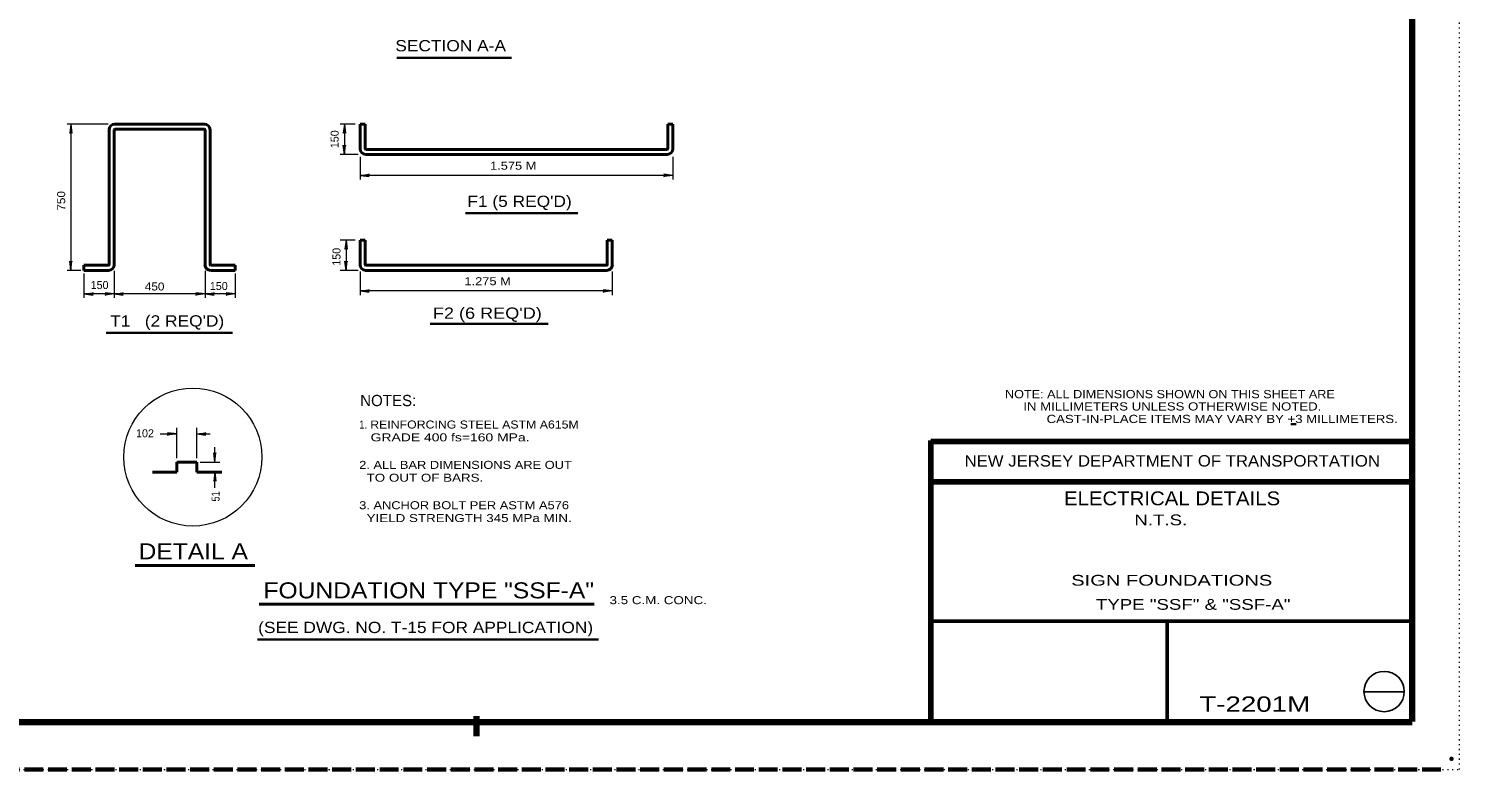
# Model space of a CAD drawing. Extents: x 312583 to 312854, y 144419 to 144597.
# Drawn here: x 312717.6 to 312853.5, y 144418.6 to 144489 of the extents above; entities that cross this region are included whole.
import ezdxf
from ezdxf.enums import TextEntityAlignment as Align

# ---------------------------------------------------------------- set-up
doc = ezdxf.new("R2010")
doc.units = 0
doc.header["$LTSCALE"] = 0.3
doc.header["$PDMODE"] = 32
doc.header["$PDSIZE"] = 0.15
doc.linetypes.add('DOTTED', pattern=[1.5, 0.3, -1.2])
doc.linetypes.add('LONG_DASHED', pattern=[7.5, 6, -1.5])
for name, color, linetype, lineweight in [('1', 7, 'Continuous', 40), ('10', 7, 'Continuous', 25), ('2', 7, 'Continuous', 13), ('62', 7, 'DOTTED', 13), ('63', 7, 'LONG_DASHED', 60)]:
    doc.layers.add(name, color=color, linetype=linetype, lineweight=lineweight)

msp = doc.modelspace()

# ---------------------------------------------------------------- linework, layer by layer
at = {"layer": '1', "lineweight": 158}
for p, q in [((312849, 144423.1446), (312849, 144585.0846)), ((312616.5, 144423.0846), (312849, 144423.0846)), ((312760.1396, 144421.7259), (312760.1396, 144423.6459))]:
    msp.add_line(p, q, dxfattribs=at)
at = {"layer": '1'}
for p, q in [((312734.2983, 144479.8873), (312725.7883, 144479.8873)), ((312749.0873, 144477.5489), (312749.0873, 144479.8873)), ((312749.0873, 144479.8873), (312749.5703, 144479.8873)), ((312749.5703, 144477.5489), (312749.5703, 144479.8873)), ((312778.3203, 144477.5489), (312778.3203, 144479.8873)), ((312778.3203, 144479.8873), (312778.7956, 144479.8873)), ((312778.7956, 144477.5489), (312778.7956, 144479.8873)), ((312725.2516, 144479.3429), (312725.2516, 144466.5319)), ((312725.7346, 144479.3429), (312725.7346, 144466.5319)), ((312734.2983, 144479.4043), (312725.7883, 144479.4043)), ((312734.3596, 144479.3429), (312734.3596, 144466.5319)), ((312734.835, 144479.3429), (312734.835, 144466.5319)), ((312749.6316, 144477.4876), (312778.259, 144477.4876)), ((312749.6316, 144477.0123), (312778.259, 144477.0123)), ((312749.0873, 144466.5319), (312749.0873, 144468.8626)), ((312749.0873, 144468.8626), (312749.5703, 144468.8626)), ((312749.5703, 144466.5319), (312749.5703, 144468.8626)), ((312772.5703, 144466.5319), (312772.5703, 144468.8626)), ((312772.5703, 144468.8626), (312773.0456, 144468.8626)), ((312773.0456, 144466.5319), (312773.0456, 144468.8626)), ((312725.1903, 144466.4706), (312722.8596, 144466.4706)), ((312722.8596, 144466.4706), (312722.8596, 144465.9876)), ((312725.1903, 144465.9876), (312722.8596, 144465.9876)), ((312737.2346, 144466.4706), (312734.8963, 144466.4706)), ((312737.2346, 144465.9876), (312734.8963, 144465.9876)), ((312737.2346, 144466.4706), (312737.2346, 144465.9876)), ((312749.6316, 144466.4706), (312772.509, 144466.4706)), ((312749.6316, 144465.9876), (312772.509, 144465.9876)), ((312731.6686, 144447.7793), (312733.5853, 144447.7793)), ((312731.6686, 144447.7793), (312731.6686, 144446.8209)), ((312733.5853, 144447.7793), (312733.5853, 144446.8209)), ((312729.3686, 144446.8209), (312731.6686, 144446.8209)), ((312733.5853, 144446.8209), (312735.962, 144446.8209))]:
    msp.add_line(p, q, dxfattribs=at)
at = {"layer": '1', "lineweight": 35}
msp.add_line((312837.5016, 144451.373), (312838.0115, 144451.373), dxfattribs=at)
at = {"layer": '1', "lineweight": 80}
for p, q in [((312803.31, 144423.1446), (312803.31, 144449.8146)), ((312803.31, 144449.7246), (312849, 144449.7246)), ((312803.31, 144445.9146), (312849, 144445.9146))]:
    msp.add_line(p, q, dxfattribs=at)
at = {"layer": '1', "lineweight": 53}
for p, q in [((312849, 144432.6666), (312803.1227, 144432.6666)), ((312825.7547, 144432.6666), (312825.7547, 144423.1446))]:
    msp.add_line(p, q, dxfattribs=at)
at = {"layer": '1', "lineweight": 25}
msp.add_line((312844.4384, 144425.966), (312848.2794, 144425.966), dxfattribs=at)
at = {"layer": '1'}
for centre, radius, start, end in [((312725.7907, 144479.3463), 0.5391, 90, 180), ((312734.2959, 144479.3463), 0.5391, 0, 90), ((312725.7907, 144479.3463), 0.0599, 90, 180), ((312734.2959, 144479.3463), 0.0599, 0, 90), ((312749.6297, 144477.5494), 0.5391, 180, 270), ((312749.6297, 144477.5494), 0.0599, 180, 270), ((312778.2599, 144477.5494), 0.5391, 270, 0), ((312778.2599, 144477.5494), 0.0599, 270, 0), ((312725.1917, 144466.5286), 0.5391, 270, 0), ((312725.1917, 144466.5286), 0.0599, 270, 0), ((312734.8949, 144466.5286), 0.5391, 180, 270), ((312734.8949, 144466.5286), 0.0599, 180, 270), ((312749.6297, 144466.5286), 0.5391, 180, 270), ((312749.6297, 144466.5286), 0.0599, 180, 270), ((312772.5099, 144466.5286), 0.5391, 270, 0), ((312772.5099, 144466.5286), 0.0599, 270, 0)]:
    msp.add_arc(centre, radius, start, end, dxfattribs=at)
msp.add_point((312852.75, 144419.5846), dxfattribs=at)
at = {"layer": '10'}
msp.add_circle((312846.3494, 144425.9805), 1.9159, dxfattribs=at)
at = {"layer": '2', "lineweight": 35}
for p, q in [((312752.5752, 144486.1933), (312763.4544, 144486.1933)), ((312759.1153, 144471.4279), (312769.762, 144471.4279)), ((312755.7496, 144460.9032), (312766.9594, 144460.9032)), ((312724.968, 144460.0612), (312736.9724, 144460.0612)), ((312739.3545, 144430.9397), (312771.7237, 144430.9397))]:
    msp.add_line(p, q, dxfattribs=at)
at = {"layer": '2'}
for p, q in [((312725.175, 144479.8873), (312721.2573, 144479.8873)), ((312721.6176, 144479.8873), (312721.5103, 144479.0209)), ((312721.6176, 144479.8873), (312721.6176, 144465.9876)), ((312721.6176, 144479.8873), (312721.725, 144479.0209)), ((312748.635, 144479.8873), (312747.186, 144479.8873)), ((312747.5923, 144479.8873), (312747.485, 144479.0209)), ((312747.5923, 144479.8873), (312747.5923, 144477.0123)), ((312747.5923, 144479.8873), (312747.6996, 144479.0209)), ((312721.5103, 144479.0209), (312721.6176, 144479.2969)), ((312721.725, 144479.0209), (312721.6176, 144479.2969)), ((312747.485, 144479.0209), (312747.5923, 144479.2969)), ((312747.6996, 144479.0209), (312747.5923, 144479.2969)), ((312748.8956, 144477.0123), (312747.186, 144477.0123)), ((312747.485, 144477.8786), (312747.5923, 144477.6026)), ((312747.5923, 144477.0123), (312747.485, 144477.8786)), ((312747.6996, 144477.8786), (312747.5923, 144477.6026)), ((312747.5923, 144477.0123), (312747.6996, 144477.8786)), ((312749.0873, 144476.7746), (312749.0873, 144474.6203)), ((312778.7956, 144476.7746), (312778.7956, 144474.6203)), ((312749.0873, 144475.0113), (312749.9536, 144475.1186)), ((312778.7956, 144475.0113), (312749.0873, 144475.0113)), ((312749.0873, 144475.0113), (312749.9536, 144474.9039)), ((312749.9536, 144475.1186), (312749.6776, 144475.0113)), ((312749.9536, 144474.9039), (312749.6776, 144475.0113)), ((312777.9293, 144475.1186), (312778.2053, 144475.0113)), ((312778.7956, 144475.0113), (312777.9293, 144475.1186)), ((312777.9293, 144474.9039), (312778.2053, 144475.0113)), ((312778.7956, 144475.0113), (312777.9293, 144474.9039)), ((312748.635, 144468.8626), (312747.186, 144468.8626)), ((312747.761, 144468.8626), (312747.6536, 144467.9963)), ((312747.761, 144468.8626), (312747.761, 144465.9876)), ((312747.761, 144468.8626), (312747.8683, 144467.9963)), ((312747.6536, 144467.9963), (312747.761, 144468.2723)), ((312747.8683, 144467.9963), (312747.761, 144468.2723)), ((312722.5683, 144465.9876), (312721.2573, 144465.9876)), ((312721.5103, 144466.8539), (312721.6176, 144466.5779)), ((312721.6176, 144465.9876), (312721.5103, 144466.8539)), ((312721.725, 144466.8539), (312721.6176, 144466.5779)), ((312721.6176, 144465.9876), (312721.725, 144466.8539)), ((312725.7346, 144465.9493), (312725.7346, 144463.3963)), ((312734.3596, 144465.9493), (312734.3596, 144463.3963)), ((312748.8956, 144465.9876), (312747.186, 144465.9876)), ((312747.6536, 144466.8539), (312747.761, 144466.5779)), ((312747.761, 144465.9876), (312747.6536, 144466.8539)), ((312747.8683, 144466.8539), (312747.761, 144466.5779)), ((312747.761, 144465.9876), (312747.8683, 144466.8539)), ((312722.8596, 144465.7039), (312722.8596, 144463.3963)), ((312737.2346, 144465.7039), (312737.2346, 144463.3963)), ((312749.0873, 144465.8726), (312749.0873, 144463.6493)), ((312773.0456, 144465.8726), (312773.0456, 144463.6493)), ((312722.8596, 144463.7489), (312723.726, 144463.8563)), ((312725.7346, 144463.7489), (312722.8596, 144463.7489)), ((312722.8596, 144463.7489), (312723.726, 144463.6416)), ((312723.726, 144463.8563), (312723.45, 144463.7489)), ((312723.726, 144463.6416), (312723.45, 144463.7489)), ((312724.8683, 144463.8563), (312725.1443, 144463.7489)), ((312725.7346, 144463.7489), (312724.8683, 144463.8563)), ((312724.8683, 144463.6416), (312725.1443, 144463.7489)), ((312725.7346, 144463.7489), (312724.8683, 144463.6416)), ((312725.7346, 144463.7489), (312726.601, 144463.8563)), ((312725.7346, 144463.7489), (312726.601, 144463.6416)), ((312726.601, 144463.8563), (312726.325, 144463.7489)), ((312726.601, 144463.6416), (312726.325, 144463.7489)), ((312733.4933, 144463.8563), (312733.7693, 144463.7489)), ((312734.3596, 144463.7489), (312733.4933, 144463.8563)), ((312733.4933, 144463.6416), (312733.7693, 144463.7489)), ((312734.3596, 144463.7489), (312733.4933, 144463.6416)), ((312734.3596, 144463.7489), (312735.226, 144463.8563)), ((312734.3596, 144463.7489), (312735.226, 144463.6416)), ((312735.226, 144463.8563), (312734.95, 144463.7489)), ((312735.226, 144463.6416), (312734.95, 144463.7489)), ((312736.3683, 144463.8563), (312736.6443, 144463.7489)), ((312737.2346, 144463.7489), (312736.3683, 144463.8563)), ((312736.3683, 144463.6416), (312736.6443, 144463.7489)), ((312737.2346, 144463.7489), (312736.3683, 144463.6416)), ((312749.0873, 144464.0403), (312749.9536, 144464.1476)), ((312773.0456, 144464.0403), (312749.0873, 144464.0403)), ((312749.0873, 144464.0403), (312749.9536, 144463.9329)), ((312749.9536, 144464.1476), (312749.6776, 144464.0403)), ((312749.9536, 144463.9329), (312749.6776, 144464.0403)), ((312772.1793, 144464.1476), (312772.4553, 144464.0403)), ((312773.0456, 144464.0403), (312772.1793, 144464.1476)), ((312772.1793, 144463.9329), (312772.4553, 144464.0403)), ((312773.0456, 144464.0403), (312772.1793, 144463.9329)), ((312731.6686, 144448.1549), (312731.6686, 144451.0376)), ((312733.5853, 144448.1549), (312733.5853, 144451.0376)), ((312730.097, 144450.4473), (312731.6686, 144450.4473)), ((312730.8023, 144450.5546), (312731.0783, 144450.4473)), ((312731.6686, 144450.4473), (312730.8023, 144450.5546)), ((312730.8023, 144450.3399), (312731.0783, 144450.4473)), ((312731.6686, 144450.4473), (312730.8023, 144450.3399)), ((312733.5853, 144450.4473), (312734.4516, 144450.5546)), ((312733.5853, 144450.4473), (312734.858, 144450.4473)), ((312733.5853, 144450.4473), (312734.4516, 144450.3399)), ((312734.4516, 144450.5546), (312734.1756, 144450.4473)), ((312734.4516, 144450.3399), (312734.1756, 144450.4473)), ((312735.1876, 144448.6456), (312735.295, 144448.3696)), ((312735.295, 144447.7793), (312735.1876, 144448.6456)), ((312735.295, 144447.7793), (312735.295, 144449.1818)), ((312735.4023, 144448.6456), (312735.295, 144448.3696)), ((312735.295, 144447.7793), (312735.4023, 144448.6456)), ((312733.8996, 144447.7793), (312735.755, 144447.7793)), ((312735.295, 144446.8209), (312735.1876, 144445.9546)), ((312735.1876, 144445.9546), (312735.295, 144446.2306)), ((312735.295, 144445.3228), (312735.295, 144446.8209)), ((312735.295, 144446.8209), (312735.4023, 144445.9546)), ((312735.4023, 144445.9546), (312735.295, 144446.2306))]:
    msp.add_line(p, q, dxfattribs=at)
at = {"layer": '2', "lineweight": 40}
for p, q in [((312727.7349, 144437.9587), (312739.0852, 144437.9587)), ((312739.5055, 144434.2783), (312771.3142, 144434.2783))]:
    msp.add_line(p, q, dxfattribs=at)
at = {"layer": '2'}
msp.add_lwpolyline([(312737.2346, 144463.7489), (312734.3596, 144463.7489), (312725.7346, 144463.7489)], dxfattribs=at)
msp.add_circle((312733.2039, 144448.2575), 6.5565, dxfattribs=at)
at = {"layer": '62'}
msp.add_lwpolyline([(312601.2, 144418.5846), (312853.5, 144418.5846), (312853.5, 144596.7846)], dxfattribs=at)
at = {"layer": '63'}
msp.add_line((312851.75, 144418.5846), (312583.526, 144418.5846), dxfattribs=at)

# ---------------------------------------------------------------- texts
at = {"layer": '1'}
for s, width, p in [('NOTE: ALL DIMENSIONS SHOWN ON THIS SHEET ARE', 1.15, (312810.3437, 144453.8482)), ('     IN MILLIMETERS UNLESS OTHERWISE NOTED.', 1.2, (312810.3436, 144452.6782)), ('CAST-IN-PLACE ITEMS MAY VARY BY +3 MILLIMETERS.', 1.2, (312814.2945, 144451.4873))]:
    msp.add_text(s, height=0.78, dxfattribs=dict(at, width=width)).set_placement(p)
for s, height, width, p in [('NEW JERSEY DEPARTMENT OF TRANSPORTATION', 1.08, 1.1, (312826.2285, 144447.3546)), ('ELECTRICAL DETAILS', 1.315, 1.1, (312826.2109, 144443.676)), ('T-2201M   ', 1.457, 1.35, (312835.1594, 144424.057))]:
    msp.add_text(s, height=height, dxfattribs=dict(at, width=width)).set_placement(p, align=Align.CENTER)
at = {"layer": '2'}
for s, height, width, p in [('SECTION A-A', 1.07, 1.15, (312757.6907, 144486.8023)), ("F1 (5 REQ'D)", 1.07, 1.15, (312764.2335, 144472.017)), ("F2 (6 REQ'D)", 1.07, 1.2, (312761.175, 144461.391)), ("T1   (2 REQ'D)", 1.07, 1.15, (312730.7662, 144460.655)), ('    N.T.S.  ', 1.02, 1.3, (312824.6461, 144441.778)), ('DETAIL A', 1.52, 1.15, (312733.2431, 144438.5412)), ('FOUNDATION TYPE "SSF-A"', 1.52, 1.15, (312755.6103, 144434.8329)), ('               SIGN FOUNDATIONS              ', 1.02, 1.4, (312825.9157, 144436.04)), ('           TYPE "SSF" & "SSF-A"          ', 1.02, 1.3, (312827.9704, 144433.7476)), ('(SEE DWG. NO. T-15 FOR APPLICATION)', 1.07, 1.15, (312755.314, 144431.537))]:
    msp.add_text(s, height=height, dxfattribs=dict(at, width=width)).set_placement(p, align=Align.CENTER)
for p in [(312747.0492, 144477.6008), (312747.2265, 144466.4369)]:
    msp.add_text('150', height=0.76, rotation=90, dxfattribs=at).set_placement(p)
for s, width, p in [('1.575 M', 1.2, (312761.4277, 144475.5533)), ('450', 1.1, (312728.6396, 144464.0803)), ('1.275 M', 1.2, (312758.9994, 144464.5822)), ('1.', 0.9, (312749.003, 144450.9676)), (' REINFORCING STEEL ASTM A615M', 1.15, (312749.7236, 144450.9676)), (' GRADE 400 fs=160 MPa.', 1.3, (312749.7236, 144449.7476)), ('2. ALL BAR DIMENSIONS ARE OUT', 1.2, (312749.003, 144447.1343)), ('  TO OUT OF BARS.', 1.25, (312749.003, 144445.9143)), ('3. ANCHOR BOLT PER ASTM A576', 1.2, (312749.003, 144443.3009)), ('  YIELD STRENGTH 345 MPa MIN.', 1.25, (312749.003, 144442.0809)), ('3.5 C.M. CONC.', 1.25, (312772.7815, 144434.2813))]:
    msp.add_text(s, height=0.76, dxfattribs=dict(at, width=width)).set_placement(p)
for s, width, p in [('750', 1.1, (312721.0768, 144471.6637)), ('51', 0.85, (312735.7423, 144444.0345))]:
    msp.add_text(s, height=0.76, rotation=90, dxfattribs=dict(at, width=width)).set_placement(p)
for s, p in [('150', (312723.5009, 144464.2208)), ('150', (312734.8193, 144464.1275)), ('102', (312727.8097, 144450.1357))]:
    msp.add_text(s, height=0.76, dxfattribs=at).set_placement(p)
msp.add_text('NOTES:', height=1.07, dxfattribs=at).set_placement((312751.7603, 144453.0926), align=Align.CENTER)

doc.saveas('drawing.dxf')
